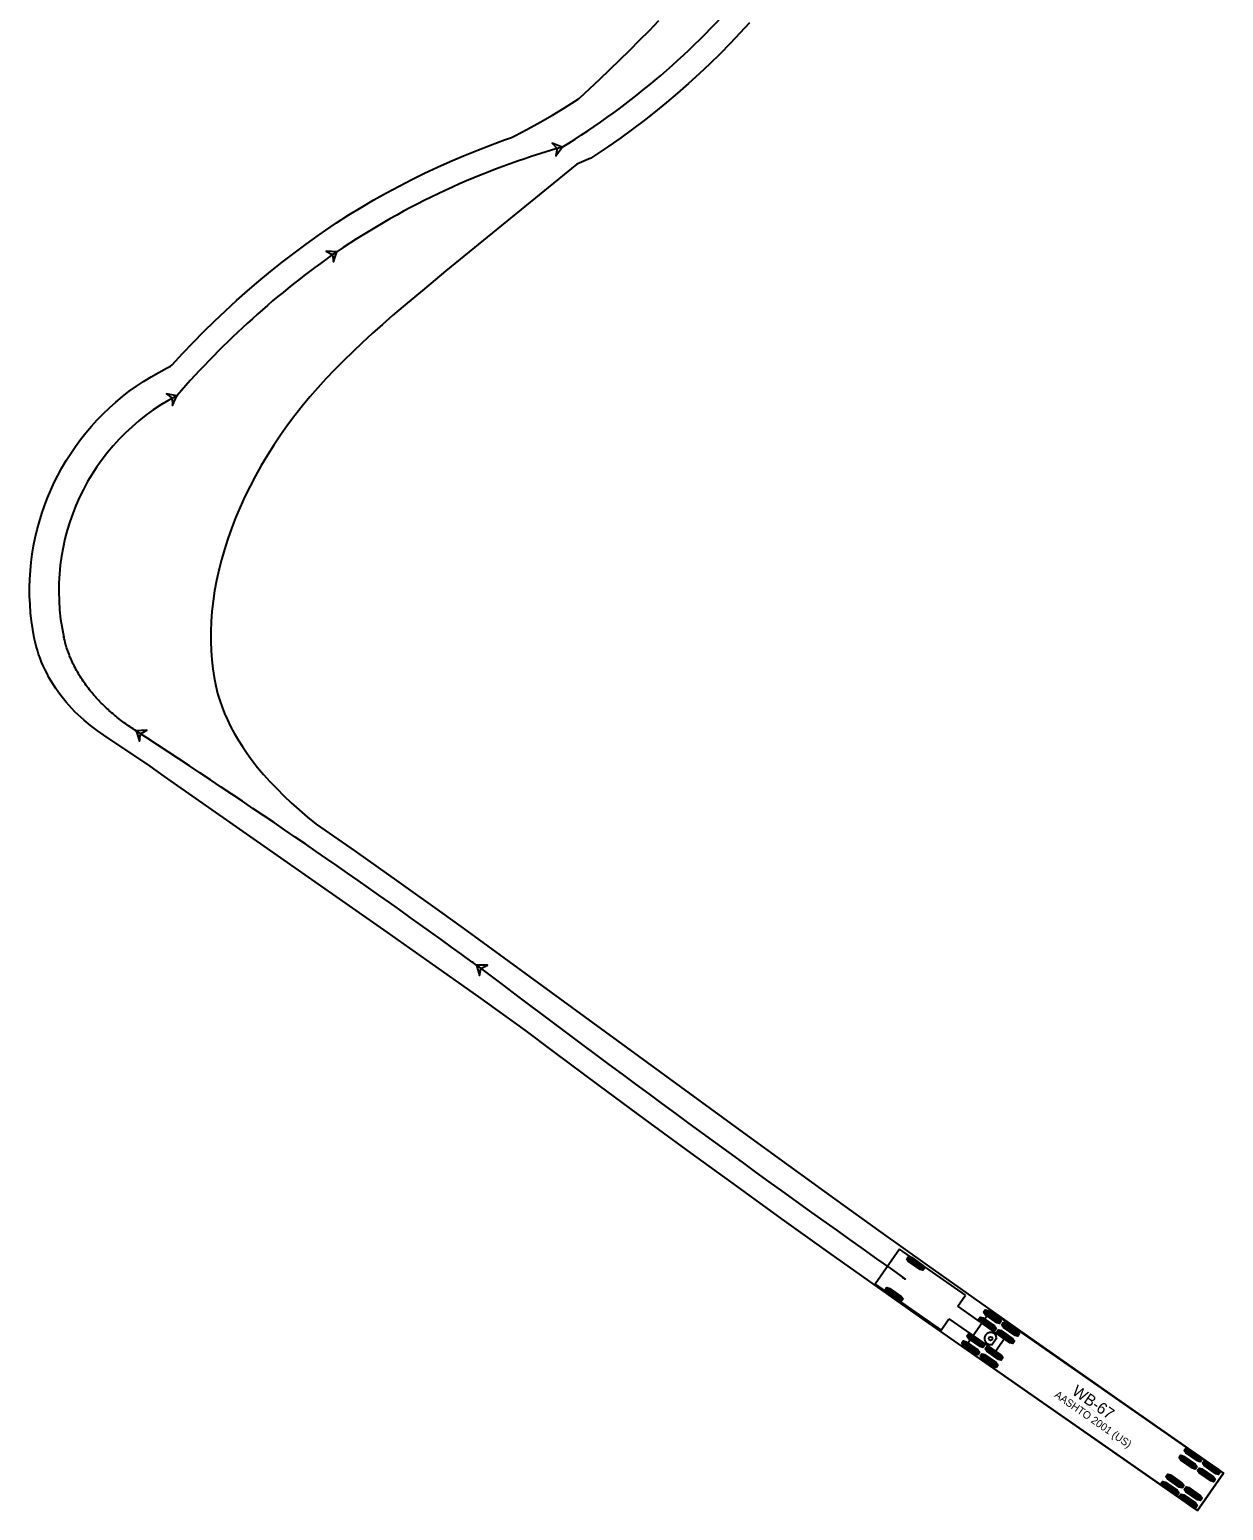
# Model space of a CAD drawing. Extents: x 973688 to 979179, y 703586 to 707602.
# Drawn here: x 978956.2 to 979179.1, y 704814.5 to 705091 of the extents above; entities that cross this region are included whole.
import ezdxf

# ---------------------------------------------------------------- set-up
doc = ezdxf.new("R2010")
doc.units = 0
doc.layers.add('0-NPLT', color=7, linetype='Continuous')

msp = doc.modelspace()

# ---------------------------------------------------------------- linework, layer by layer
at = {"layer": '0-NPLT'}
for p, q in [((979118.65, 704863.29), (979114.08, 704856.72)), ((979130.96, 704854.71), (979118.65, 704863.29)), ((979120.03, 704861.48), (979123.04, 704859.39)), ((979120.16, 704861.67), (979123.17, 704859.58)), ((979120.3, 704861.86), (979123.3, 704859.76)), ((979114.08, 704856.72), (979126.38, 704848.15)), ((979114.08, 704856.72), (979114.08, 704856.72)), ((979115.98, 704855.67), (979118.99, 704853.58)), ((979116.12, 704855.86), (979119.12, 704853.76)), ((979116.25, 704856.05), (979119.25, 704853.95)), ((979129.49, 704852.61), (979130.96, 704854.71)), ((979138.17, 704846.55), (979129.49, 704852.61)), ((979126.38, 704848.15), (979127.85, 704850.25)), ((979127.85, 704850.25), (979136.53, 704844.2)), ((979135.61, 704851.77), (979130.75, 704844.8)), ((979133.38, 704850.17), (979136.39, 704848.08)), ((979133.51, 704850.36), (979136.52, 704848.26)), ((979133.64, 704850.55), (979136.65, 704848.45)), ((979134.32, 704851.53), (979137.33, 704849.43)), ((979134.45, 704851.71), (979137.46, 704849.62)), ((979134.59, 704851.9), (979137.59, 704849.81)), ((979179.1, 704821.47), (979135.61, 704851.77)), ((979138, 704849.52), (979141.01, 704847.42)), ((979131.22, 704847.07), (979134.23, 704844.97)), ((979131.35, 704847.26), (979134.36, 704845.16)), ((979131.48, 704847.44), (979134.49, 704845.35)), ((979135.84, 704845.44), (979136.77, 704846.77)), ((979136.8, 704847.79), (979139.81, 704845.69)), ((979136.93, 704847.98), (979139.94, 704845.88)), ((979137.06, 704848.17), (979140.07, 704846.07)), ((979137.74, 704849.14), (979140.75, 704847.05)), ((979137.87, 704849.33), (979140.88, 704847.24)), ((979130.27, 704845.72), (979133.28, 704843.62)), ((979130.4, 704845.9), (979133.41, 704843.81)), ((979130.54, 704846.09), (979133.54, 704843.99)), ((979130.75, 704844.8), (979174.24, 704814.5)), ((979130.75, 704844.8), (979130.75, 704844.8)), ((979134.64, 704844.69), (979137.64, 704842.59)), ((979134.77, 704844.87), (979137.77, 704842.78)), ((979134.9, 704845.06), (979137.91, 704842.97)), ((979136.53, 704844.2), (979138.17, 704846.55)), ((979133.69, 704843.33), (979136.7, 704841.24)), ((979133.82, 704843.52), (979136.83, 704841.42)), ((979133.95, 704843.71), (979136.96, 704841.61)), ((979170.98, 704824.55), (979173.99, 704822.46)), ((979171.12, 704824.74), (979174.12, 704822.64)), ((979171.8, 704825.72), (979174.8, 704823.62)), ((979171.93, 704825.91), (979174.94, 704823.81)), ((979172.06, 704826.09), (979175.07, 704824)), ((979170.85, 704824.36), (979173.86, 704822.27)), ((979174.27, 704821.98), (979177.28, 704819.89)), ((979174.4, 704822.17), (979177.41, 704820.07)), ((979174.53, 704822.36), (979177.54, 704820.26)), ((979175.22, 704823.34), (979178.22, 704821.24)), ((979175.35, 704823.52), (979178.35, 704821.43)), ((979175.48, 704823.71), (979178.49, 704821.62)), ((979167.46, 704819.5), (979170.47, 704817.4)), ((979167.59, 704819.68), (979170.6, 704817.59)), ((979167.72, 704819.87), (979170.73, 704817.78)), ((979168.4, 704820.85), (979171.41, 704818.75)), ((979168.54, 704821.04), (979171.54, 704818.94)), ((979168.67, 704821.23), (979171.67, 704819.13)), ((979174.24, 704814.5), (979179.1, 704821.47)), ((979170.88, 704817.11), (979173.89, 704815.02)), ((979171.01, 704817.3), (979174.02, 704815.21)), ((979171.14, 704817.49), (979174.15, 704815.39)), ((979171.82, 704818.47), (979174.83, 704816.37)), ((979171.95, 704818.66), (979174.96, 704816.56)), ((979172.08, 704818.84), (979175.09, 704816.75))]:
    msp.add_line(p, q, dxfattribs=at)
for points in [[(979174.1, 704814.59), (979140.13, 704838.26), (979122.88, 704850.31), (979114.14, 704856.46), (979105.42, 704862.66), (979096.73, 704868.88), (979088.23, 704875.02), (979079.71, 704881.21), (979071.13, 704887.51), (979062.57, 704893.83), (979054.04, 704900.18), (979048.72, 704904.17), (979040.09, 704910.36), (979031.45, 704916.49), (979022.98, 704922.45), (978981.42, 704951.51), (978978.7, 704953.48), (978970.07, 704959.25), (978968.81, 704960.12), (978967.58, 704961.05), (978966.38, 704962.04), (978965.27, 704963.06), (978964.69, 704963.63), (978964.13, 704964.21), (978963.58, 704964.8), (978963.05, 704965.41), (978962.53, 704966.04), (978962.04, 704966.67), (978961.56, 704967.32), (978961.1, 704967.98), (978960.66, 704968.66), (978960.24, 704969.34), (978959.84, 704970.03), (978959.47, 704970.74), (978959.11, 704971.45), (978958.78, 704972.17), (978958.46, 704972.9), (978958.17, 704973.64), (978957.91, 704974.38), (978957.67, 704975.13), (978957.45, 704975.89), (978957.25, 704976.65), (978957.08, 704977.42), (978956.8, 704978.96), (978956.58, 704980.51), (978956.41, 704982.08), (978956.3, 704983.65), (978956.23, 704985.23), (978956.23, 704986.81), (978956.27, 704988.39), (978956.37, 704989.97), (978956.52, 704991.55), (978956.72, 704993.04), (978956.97, 704994.58), (978957.27, 704996.11), (978957.63, 704997.63), (978958.04, 704999.13), (978958.49, 705000.62), (978959, 705002.1), (978959.55, 705003.55), (978960.16, 705004.99), (978960.81, 705006.41), (978961.49, 705007.76), (978962.24, 705009.15), (978963.05, 705010.52), (978963.9, 705011.86), (978964.8, 705013.17), (978965.74, 705014.46), (978966.73, 705015.71), (978967.77, 705016.92), (978968.84, 705018.11), (978969.96, 705019.26), (978971.12, 705020.37), (978972.32, 705021.44), (978973.56, 705022.47), (978974.84, 705023.46), (978976.15, 705024.42), (978977.51, 705025.32), (978978.9, 705026.19), (978980.33, 705027), (978981.79, 705027.77), (978982.54, 705028.14), (978982.81, 705028.38), (978984.77, 705030.51), (978986.76, 705032.6), (978988.76, 705034.63), (978990.76, 705036.58), (978992.79, 705038.51), (978994.84, 705040.39), (978996.93, 705042.23), (978999.03, 705044.03), (979001.18, 705045.81), (979003.38, 705047.56), (979005.59, 705049.27), (979007.83, 705050.94), (979010.08, 705052.56), (979012.35, 705054.13), (979013.49, 705054.9), (979015.8, 705056.38), (979018.13, 705057.8), (979020.48, 705059.18), (979022.84, 705060.51), (979025.23, 705061.79), (979027.61, 705063.02), (979029.97, 705064.18), (979032.36, 705065.3), (979034.77, 705066.39), (979037.22, 705067.44), (979039.71, 705068.45), (979042.28, 705069.44), (979044.9, 705070.4), (979046.22, 705070.86), (979046.83, 705071.15), (979049.19, 705072.41), (979051.53, 705073.7), (979053.83, 705075.04), (979056.1, 705076.41), (979058.61, 705078.01), (979058.87, 705078.21), (979062.68, 705081.76), (979064.57, 705083.55), (979066.43, 705085.35), (979068.28, 705087.17), (979070.11, 705089.01), (979071.93, 705090.86), (979073.72, 705092.72)], [(979090.6, 705092.26), (979088.82, 705090.31), (979087.01, 705088.39), (979085.13, 705086.48), (979083.2, 705084.59), (979081.24, 705082.74), (979079.24, 705080.92), (979077.21, 705079.13), (979075.15, 705077.39), (979073.05, 705075.68), (979070.93, 705074.02), (979068.77, 705072.39), (979066.58, 705070.8), (979064.36, 705069.25), (979062.11, 705067.75), (979060.98, 705067.01), (979058.4, 705065.88), (979033.96, 705045.93), (979029.92, 705042.6), (979025.95, 705039.27), (979024, 705037.59), (979022.08, 705035.91), (979020.19, 705034.23), (979018.34, 705032.54), (979016.54, 705030.84), (979014.8, 705029.14), (979013.14, 705027.47), (979011.55, 705025.8), (979010.02, 705024.12), (979008.55, 705022.43), (979007.13, 705020.71), (979005.72, 705018.93), (979004.37, 705017.12), (979003.06, 705015.28), (979001.81, 705013.42), (979000.62, 705011.53), (978999.48, 705009.63), (978998.4, 705007.7), (978997.37, 705005.76), (978996.41, 705003.8), (978995.52, 705001.83), (978994.68, 704999.86), (978993.91, 704997.87), (978993.21, 704995.88), (978992.59, 704993.94), (978992.04, 704992), (978991.55, 704990.06), (978991.13, 704988.14), (978990.77, 704986.21), (978990.48, 704984.27), (978990.26, 704982.35), (978990.11, 704980.46), (978990.03, 704978.61), (978990.03, 704976.79), (978990.09, 704975.02), (978990.22, 704973.3), (978990.41, 704971.63), (978990.67, 704970.03), (978990.98, 704968.49), (978991.33, 704967.06), (978991.72, 704965.73), (978992.15, 704964.48), (978992.62, 704963.27), (978993.14, 704962.1), (978993.73, 704960.88), (978994.4, 704959.64), (978995.13, 704958.38), (978995.94, 704957.11), (978996.82, 704955.82), (978997.77, 704954.53), (978998.8, 704953.22), (978999.91, 704951.91), (979001.09, 704950.59), (979002.35, 704949.27), (979003.68, 704947.94), (979005.08, 704946.61), (979006.55, 704945.29), (979008.09, 704943.96), (979009.7, 704942.63), (979017.01, 704937.56), (979025.18, 704931.81), (979033.63, 704925.78), (979037.86, 704922.73), (979089.48, 704885.01), (979097.88, 704878.9), (979106.47, 704872.69), (979115.13, 704866.47), (979123.82, 704860.27), (979132.52, 704854.1), (979141.23, 704847.94), (979158.71, 704835.69), (979179.1, 704821.47), (979174.24, 704814.5), (979174.1, 704814.59), (979174.1, 704814.59)], [(979055.66, 705069.05), (979053.8, 705069.79), (979054.69, 705068.78), (979054.46, 705067.45), (979055.66, 705069.05)], [(979013.58, 705049.52), (979011.58, 705049.62), (979012.76, 705048.95), (979012.98, 705047.62), (979013.58, 705049.52)], [(978983.73, 705022.64), (978981.76, 705022.98), (978982.84, 705022.17), (978982.88, 705020.82), (978983.73, 705022.64)], [(978976.09, 704960.04), (978975.81, 704960.23), (978975.53, 704960.41), (978975.25, 704960.6), (978974.98, 704960.78), (978974.7, 704960.97), (978974.43, 704961.16), (978974.16, 704961.36), (978973.89, 704961.56), (978973.62, 704961.75), (978973.36, 704961.95), (978973.09, 704962.16), (978972.83, 704962.36), (978972.57, 704962.57), (978972.31, 704962.78), (978972.05, 704962.99), (978971.8, 704963.21), (978971.54, 704963.42), (978971.29, 704963.64), (978971.04, 704963.87), (978970.8, 704964.09), (978970.55, 704964.32), (978970.31, 704964.54), (978970.07, 704964.78), (978969.83, 704965.01), (978969.6, 704965.25), (978969.36, 704965.48), (978969.13, 704965.73), (978968.91, 704965.97), (978968.68, 704966.21), (978968.46, 704966.46), (978968.24, 704966.71), (978968.02, 704966.97), (978967.81, 704967.22), (978967.6, 704967.48), (978967.39, 704967.74), (978967.19, 704968), (978966.98, 704968.27), (978966.79, 704968.54), (978966.59, 704968.81), (978966.4, 704969.08), (978966.21, 704969.35), (978966.02, 704969.63), (978965.84, 704969.91), (978965.66, 704970.19), (978965.49, 704970.48), (978965.32, 704970.76), (978965.15, 704971.05), (978964.99, 704971.34), (978964.83, 704971.63), (978964.67, 704971.93), (978964.52, 704972.23), (978964.37, 704972.53), (978964.23, 704972.83), (978964.09, 704973.13), (978963.96, 704973.43), (978963.82, 704973.74), (978963.7, 704974.05), (978963.58, 704974.36), (978963.46, 704974.67), (978963.35, 704974.98), (978963.24, 704975.3), (978963.13, 704975.62), (978963.04, 704975.93), (978962.94, 704976.25), (978962.85, 704976.58), (978962.77, 704976.9), (978962.69, 704977.22), (978962.61, 704977.55)], [(978976.09, 704960.04), (978976.75, 704958.16), (978976.93, 704959.5), (978978.08, 704960.2), (978976.09, 704960.04)], [(979039.68, 704916.29), (979039.41, 704916.49), (979039.15, 704916.69), (979038.88, 704916.89)], [(979039.68, 704916.29), (979040.21, 704914.36), (979040.48, 704915.69), (979041.68, 704916.3), (979039.68, 704916.29)], [(979119.64, 704857.72), (979119.37, 704857.91)]]:
    msp.add_lwpolyline(points, dxfattribs=at)
for points in [[(979055.66, 705069.05), (979053.8, 705069.79), (979054.69, 705068.78), (979054.46, 705067.45)], [(979013.58, 705049.52), (979011.58, 705049.62), (979012.76, 705048.95), (979012.98, 705047.62)], [(978983.73, 705022.64), (978981.76, 705022.98), (978982.84, 705022.17), (978982.88, 705020.82)], [(978976.09, 704960.04), (978976.75, 704958.16), (978976.93, 704959.5), (978978.08, 704960.2)], [(979039.68, 704916.29), (979040.21, 704914.36), (979040.48, 704915.69), (979041.68, 704916.3)], [(979120, 704861.44), (979120.33, 704861.91), (979120.85, 704861.75), (979123.01, 704860.25), (979123.34, 704859.81), (979123.01, 704859.34), (979122.49, 704859.49), (979120.32, 704861)], [(979115.95, 704855.63), (979116.28, 704856.1), (979116.8, 704855.94), (979118.96, 704854.43), (979119.29, 704854), (979118.96, 704853.53), (979118.44, 704853.68), (979116.27, 704855.19)], [(979133.35, 704850.13), (979133.67, 704850.6), (979134.19, 704850.44), (979136.36, 704848.93), (979136.68, 704848.5), (979136.36, 704848.03), (979135.84, 704848.18), (979133.67, 704849.69)], [(979134.29, 704851.48), (979134.62, 704851.95), (979135.14, 704851.8), (979137.3, 704850.29), (979137.63, 704849.85), (979137.3, 704849.38), (979136.78, 704849.54), (979134.61, 704851.05)], [(979137.71, 704849.1), (979138.04, 704849.57), (979138.56, 704849.42), (979140.72, 704847.91), (979141.04, 704847.47), (979140.72, 704847), (979140.2, 704847.15), (979138.03, 704848.66)], [(979131.18, 704847.02), (979131.51, 704847.49), (979132.03, 704847.34), (979134.2, 704845.83), (979134.52, 704845.4), (979134.19, 704844.93), (979133.67, 704845.08), (979131.51, 704846.59)], [(979136.77, 704847.74), (979137.09, 704848.21), (979137.61, 704848.06), (979139.78, 704846.55), (979140.1, 704846.12), (979139.77, 704845.65), (979139.25, 704845.8), (979137.09, 704847.31)], [(979130.24, 704845.67), (979130.57, 704846.14), (979131.09, 704845.99), (979133.25, 704844.48), (979133.58, 704844.04), (979133.25, 704843.57), (979132.73, 704843.72), (979130.56, 704845.23)], [(979134.6, 704844.64), (979134.93, 704845.11), (979135.45, 704844.96), (979137.62, 704843.45), (979137.94, 704843.01), (979137.61, 704842.54), (979137.09, 704842.7), (979134.93, 704844.21)], [(979133.66, 704843.29), (979133.99, 704843.76), (979134.51, 704843.6), (979136.67, 704842.09), (979136.99, 704841.66), (979136.67, 704841.19), (979136.15, 704841.34), (979133.98, 704842.85)], [(979170.82, 704824.32), (979171.15, 704824.79), (979171.67, 704824.64), (979173.83, 704823.13), (979174.16, 704822.69), (979173.83, 704822.22), (979173.31, 704822.37), (979171.14, 704823.88)], [(979171.76, 704825.67), (979172.09, 704826.14), (979172.61, 704825.99), (979174.78, 704824.48), (979175.1, 704824.04), (979174.77, 704823.58), (979174.25, 704823.73), (979172.09, 704825.24)], [(979174.24, 704821.94), (979174.57, 704822.41), (979175.09, 704822.25), (979177.25, 704820.74), (979177.57, 704820.31), (979177.25, 704819.84), (979176.73, 704819.99), (979174.56, 704821.5)], [(979175.18, 704823.29), (979175.51, 704823.76), (979176.03, 704823.61), (979178.2, 704822.1), (979178.52, 704821.66), (979178.19, 704821.19), (979177.67, 704821.35), (979175.51, 704822.85)], [(979167.43, 704819.45), (979167.76, 704819.92), (979168.28, 704819.77), (979170.44, 704818.26), (979170.76, 704817.82), (979170.44, 704817.35), (979169.92, 704817.51), (979167.75, 704819.02)], [(979168.37, 704820.8), (979168.7, 704821.27), (979169.22, 704821.12), (979171.38, 704819.61), (979171.71, 704819.18), (979171.38, 704818.71), (979170.86, 704818.86), (979168.69, 704820.37)], [(979170.85, 704817.07), (979171.17, 704817.54), (979171.69, 704817.39), (979173.86, 704815.88), (979174.18, 704815.44), (979173.86, 704814.97), (979173.34, 704815.12), (979171.17, 704816.63)], [(979171.79, 704818.42), (979172.12, 704818.89), (979172.64, 704818.74), (979174.8, 704817.23), (979175.13, 704816.79), (979174.8, 704816.33), (979174.28, 704816.48), (979172.11, 704817.99)]]:
    msp.add_lwpolyline(points, close=True, dxfattribs=at)
for centre, radius in [((979055.66, 705069.05), 0.0417), ((979055.66, 705069.05), 0.0417), ((979013.58, 705049.52), 0.0417), ((979013.58, 705049.52), 0.0417), ((978983.73, 705022.64), 0.0417), ((978983.73, 705022.64), 0.0417), ((978962.61, 704977.55), 0.0417), ((978962.61, 704977.55), 0.0417), ((978976.09, 704960.04), 0.0417), ((978976.09, 704960.04), 0.0417), ((979038.88, 704916.89), 0.0417), ((979038.88, 704916.89), 0.0417), ((979039.68, 704916.29), 0.0417), ((979039.68, 704916.29), 0.0417), ((979119.37, 704857.91), 0.0417), ((979119.37, 704857.91), 0.0417), ((979119.64, 704857.72), 0.0417), ((979135.64, 704846.57), 0.34)]:
    msp.add_circle(centre, radius, dxfattribs=at)
for centre, radius, start, end in [((978982.03, 705189.62), 141.27, 301.4101, 319.9095), ((979094.79, 704929.61), 144.82, 105.6784, 124.1083), ((979105.47, 704917.47), 160.88, 124.833, 139.1795), ((979002.67, 704986.28), 41, 117.5221, 192.2927), ((978194.62, 703755.69), 1435.67, 53.98075, 57.02176), ((980798.46, 707233.37), 2908.97, 232.79966, 234.74554), ((979135.64, 704846.57), 1.14, 10.1296, 280.1296)]:
    msp.add_arc(centre, radius, start, end, dxfattribs=at)

# ---------------------------------------------------------------- texts
for s, height, p in [('AASHTO 2001 (US)', 1.4167, (979147.42, 704835.77)), ('WB-67', 2.125, (979150.66, 704836.31)), ('(c) 2022 Transoft Solutions, Inc. All rights reserved.', 0.085, (979153.47, 704834.09))]:
    msp.add_text(s, height=height, rotation=325.1296, dxfattribs=at).set_placement(p)

doc.saveas('drawing.dxf')
